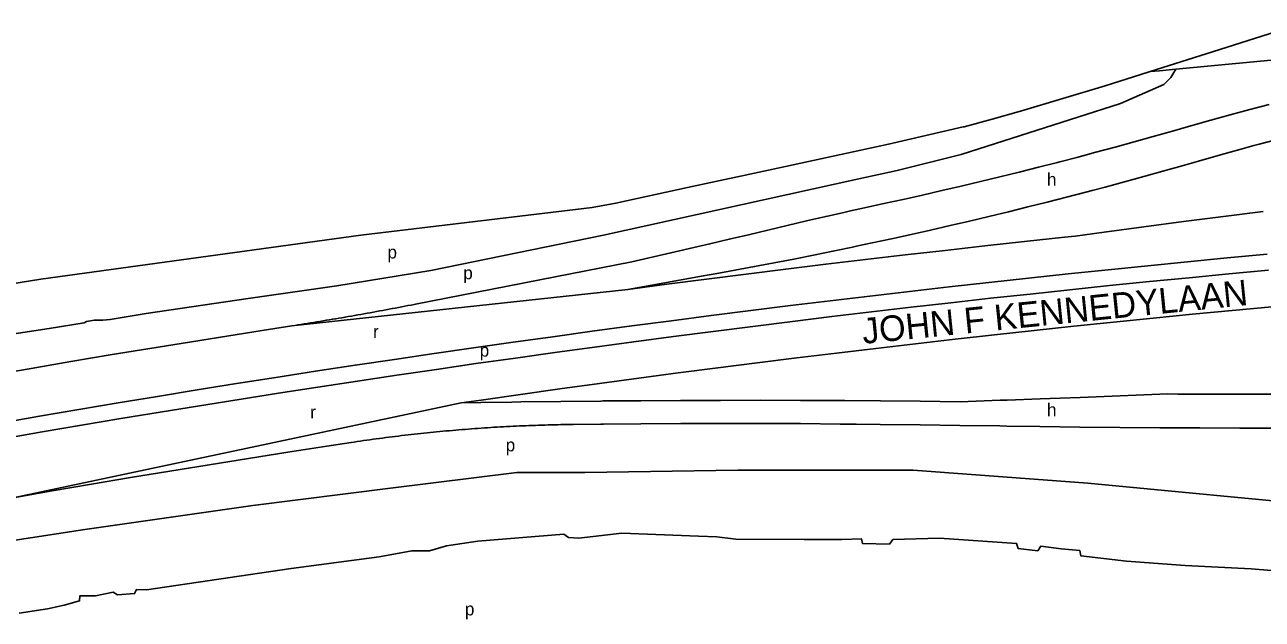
# Model space of a CAD drawing. Extents: x 159441 to 162086, y 388175 to 389787.
# Drawn here: x 159765.8 to 160153.1, y 389558.4 to 389744.4 of the extents above; entities that cross this region are included whole.
import ezdxf

# ---------------------------------------------------------------- set-up
doc = ezdxf.new("R2010")
doc.units = 0
for name, color, linetype in [('BLT_Basislijn', 7, 'Continuous'), ('BLT_Centroide', 7, 'Continuous'), ('BLT_Gemeentegrens', 7, 'Continuous'), ('BLT_Straatnaam_hoofdweg', 7, 'Continuous'), ('BLT_Vlakafsluiter', 7, 'Continuous')]:
    doc.layers.add(name, color=color, linetype=linetype)

msp = doc.modelspace()

# ---------------------------------------------------------------- linework, layer by layer
at = {"layer": 'BLT_Basislijn'}
msp.add_line((159941.02, 389604.39), (159988.95, 389605.07), dxfattribs=at)
for points in [[(160126, 389730.55), (160158.09, 389733.58), (160166.51, 389737), (160168.16, 389739.95), (160166.51, 389742.96), (160164.08, 389744.45)], [(160026.82, 389696.21), (160038.79, 389698.87), (160050.09, 389701.64), (160058.89, 389703.83), (160108.67, 389719.79), (160122.26, 389725.73), (160124.46, 389727.97), (160126, 389730.55)], [(160120.88, 389730.04), (160126, 389730.55)], [(160117.98, 389729.78), (160120.88, 389730.04)], [(160089.75, 389701.59), (160095.02, 389702.96), (160096.96, 389703.47), (160101.02, 389704.55), (160107.01, 389706.16), (160113, 389707.79), (160118.98, 389709.46), (160124.95, 389711.14), (160130.02, 389712.59), (160137.01, 389714.58), (160143.09, 389716.27), (160149.19, 389717.92), (160155.29, 389719.53)], [(160150.5, 389706.62), (160152.09, 389707.05), (160158.13, 389708.64)], [(159954.53, 389661.65), (159969.56, 389664.35), (159978.12, 389665.86), (159981.87, 389666.53), (159988.02, 389667.64), (159994.17, 389668.79), (160000.31, 389669.95), (160006.45, 389671.14), (160012.58, 389672.36), (160018.71, 389673.6), (160019.76, 389673.82), (160024.84, 389674.87), (160026.52, 389675.23), (160030.95, 389676.17), (160037.07, 389677.49), (160043.17, 389678.83), (160049.27, 389680.2), (160055.37, 389681.6), (160061.46, 389683.02), (160067.54, 389684.47), (160073.62, 389685.94), (160079.69, 389687.43), (160085.76, 389688.96), (160091.82, 389690.51), (160097.87, 389692.08), (160099.83, 389692.59), (160103.91, 389693.68), (160109.95, 389695.3), (160115.99, 389696.95), (160122.01, 389698.62), (160128.03, 389700.32), (160133.14, 389701.79), (160140.05, 389703.75), (160146.06, 389705.42), (160150.5, 389706.62)], [(159849.39, 389650.25), (159850.24, 389650.39), (159851.22, 389650.54), (159852.21, 389650.69), (159853.2, 389650.85), (159854.19, 389651.01), (159855.17, 389651.17), (159856.16, 389651.33), (159857.15, 389651.49), (159858.14, 389651.65), (159859.12, 389651.81), (159860.11, 389651.97), (159861.09, 389652.14), (159862.08, 389652.3), (159863.07, 389652.47), (159864.05, 389652.63), (159865.04, 389652.8), (159866.02, 389652.97), (159867.01, 389653.14), (159868, 389653.31), (159868.98, 389653.48), (159869.97, 389653.66), (159870.95, 389653.83), (159871.93, 389654.01), (159872.92, 389654.18), (159873.9, 389654.36), (159874.89, 389654.54), (159875.87, 389654.72), (159876.86, 389654.9), (159877.84, 389655.08), (159878.82, 389655.26), (159879.81, 389655.44), (159880.79, 389655.62), (159881.77, 389655.81), (159882.75, 389655.99), (159883.74, 389656.18), (159884.72, 389656.37), (159885.7, 389656.56), (159886.68, 389656.75), (159887.66, 389656.94), (159888.03, 389657.01), (159955.78, 389670.3), (159968, 389673.07), (159976.5, 389675.02), (159980.19, 389675.88), (159986.25, 389677.31), (159992.3, 389678.75), (159998.34, 389680.2), (160004.39, 389681.65), (160010.43, 389683.07), (160016.48, 389684.48), (160017.52, 389684.71), (160022.54, 389685.85), (160024.21, 389686.22), (160028.6, 389687.17), (160034.67, 389688.48), (160040.73, 389689.81), (160046.79, 389691.17), (160052.84, 389692.56), (160058.88, 389693.97), (160064.92, 389695.41), (160070.95, 389696.87), (160076.98, 389698.35), (160083, 389699.86), (160089.01, 389701.4), (160089.75, 389701.59)], [(159759.03, 389647.27), (159773.42, 389649.38), (159784.3, 389651.17), (159785.08, 389651.6), (159787.57, 389652.05), (159790.2, 389652.03), (159792.48, 389652.2), (159803.76, 389654.1), (159835.69, 389658.82), (159863.4, 389662.74), (159892.89, 389667.6), (159946.86, 389678.6), (160026.82, 389696.21)], [(160153.35, 389686.07), (160140.91, 389684.48), (160128.47, 389682.86), (160116.03, 389681.22), (160103.6, 389679.54), (160094.56, 389678.29), (160091.17, 389677.94), (160078.7, 389676.61), (160066.24, 389675.25), (160053.79, 389673.86), (160041.33, 389672.44), (160028.88, 389670.98), (160016.44, 389669.5), (160003.99, 389667.98), (159991.56, 389666.44), (159979.12, 389664.86), (159966.69, 389663.25), (159954.53, 389661.65)], [(160154.59, 389672.66), (160142.14, 389671.49), (160129.69, 389670.29), (160117.25, 389669.06), (160104.81, 389667.8), (160092.37, 389666.5), (160079.94, 389665.18), (160067.5, 389663.82), (160055.08, 389662.43), (160042.65, 389661.01), (160030.23, 389659.56), (160017.81, 389658.08), (160005.4, 389656.57), (159992.99, 389655.03), (159980.58, 389653.45), (159968.18, 389651.85), (159955.78, 389650.21), (159943.39, 389648.55), (159931, 389646.85), (159918.61, 389645.12), (159906.23, 389643.36), (159893.86, 389641.57), (159881.48, 389639.75), (159869.12, 389637.89), (159856.75, 389636.01), (159844.39, 389634.1), (159832.04, 389632.15), (159819.69, 389630.17), (159807.35, 389628.17), (159795.01, 389626.13), (159782.68, 389624.06), (159770.35, 389621.96), (159758.03, 389619.83)], [(159758.89, 389614.9), (159771.2, 389617.03), (159783.51, 389619.13), (159795.83, 389621.2), (159808.16, 389623.23), (159820.49, 389625.24), (159832.83, 389627.21), (159845.17, 389629.16), (159857.51, 389631.07), (159869.86, 389632.95), (159882.22, 389634.8), (159894.58, 389636.62), (159906.94, 389638.41), (159919.31, 389640.17), (159931.68, 389641.89), (159944.06, 389643.59), (159956.44, 389645.26), (159968.83, 389646.89), (159981.22, 389648.49), (159993.61, 389650.07), (160006.01, 389651.61), (160018.41, 389653.12), (160030.82, 389654.6), (160043.22, 389656.05), (160055.64, 389657.46), (160068.05, 389658.85), (160080.47, 389660.2), (160092.89, 389661.53), (160105.32, 389662.82), (160117.75, 389664.08), (160130.18, 389665.31), (160142.62, 389666.51), (160155.05, 389667.68)], [(159902.33, 389626.13), (159908.57, 389627.03), (159920.91, 389628.78), (159933.26, 389630.5), (159945.61, 389632.2), (159957.96, 389633.86), (159970.32, 389635.49), (159982.68, 389637.09), (159995.04, 389638.66), (160007.41, 389640.19), (160019.79, 389641.7), (160032.16, 389643.18), (160044.54, 389644.62), (160056.93, 389646.04), (160069.31, 389647.42), (160081.7, 389648.77), (160094.1, 389650.09), (160106.5, 389651.38), (160118.9, 389652.64), (160131.3, 389653.87), (160143.71, 389655.07), (160156.12, 389656.23)], [(159849.39, 389650.25), (159842.05, 389649.11), (159829.66, 389647.16), (159817.27, 389645.18), (159804.89, 389643.17), (159792.52, 389641.12), (159780.15, 389639.05), (159767.78, 389636.94), (159755.42, 389634.8)], [(159902.33, 389626.13), (159908.55, 389626.23), (159918.18, 389626.39), (159921.05, 389626.43), (159933.55, 389626.59), (159946.05, 389626.72), (159946.83, 389626.73), (159958.55, 389626.82), (159971.05, 389626.89), (159983.55, 389626.93), (159996.05, 389626.94), (160008.55, 389626.91), (160021.05, 389626.86), (160022.4, 389626.85), (160033.55, 389626.77), (160046.05, 389626.65), (160058.55, 389626.5), (160071.06, 389626.94), (160073.22, 389627.01), (160083.57, 389627.36), (160096.07, 389627.82), (160108.57, 389628.3), (160121.07, 389628.82), (160123.56, 389628.93), (160126.62, 389628.91), (160133.56, 389628.88), (160146.05, 389628.84), (160158.54, 389628.84)], [(160435.33, 389622.54), (160408.56, 389615.14), (160385.5, 389605.96), (160364.33, 389592.24), (160345.18, 389582), (160331.29, 389576.51), (160312.03, 389571.36), (160292.43, 389569.68), (160273.62, 389570.35), (160257.61, 389573.71), (160211.13, 389589.28), (160174.96, 389593.76), (160098.47, 389601.03), (160043.82, 389605.07), (159988.95, 389605.07)], [(159762.09, 389596.48), (159774.36, 389598.6), (159786.63, 389600.69), (159798.9, 389602.75), (159811.18, 389604.78), (159823.47, 389606.78), (159835.76, 389608.74), (159848.05, 389610.68), (159860.35, 389612.58), (159867.87, 389613.73), (159868.85, 389613.88), (159869.84, 389614.03), (159870.83, 389614.18), (159871.82, 389614.32), (159872.81, 389614.46), (159873.8, 389614.6), (159874.79, 389614.74), (159875.78, 389614.87), (159876.78, 389615.01), (159877.77, 389615.14), (159878.76, 389615.27), (159879.75, 389615.39), (159880.74, 389615.52), (159881.73, 389615.64), (159882.73, 389615.77), (159883.72, 389615.89), (159884.71, 389616), (159885.71, 389616.12), (159886.7, 389616.23), (159887.69, 389616.34), (159888.69, 389616.45), (159889.68, 389616.56), (159890.68, 389616.67), (159891.67, 389616.77), (159892.67, 389616.87), (159893.66, 389616.97), (159894.66, 389617.07), (159895.65, 389617.17), (159896.65, 389617.26), (159897.64, 389617.35), (159898.64, 389617.44), (159899.63, 389617.53), (159900.63, 389617.61), (159901.63, 389617.7), (159902.62, 389617.78), (159903.62, 389617.86), (159904.62, 389617.94), (159905.61, 389618.01), (159906.61, 389618.09), (159907.61, 389618.16), (159908.61, 389618.23), (159909.6, 389618.3), (159910.6, 389618.36), (159911.6, 389618.43), (159912.6, 389618.49), (159913.6, 389618.55), (159914.6, 389618.61), (159915.59, 389618.66), (159916.59, 389618.72), (159917.59, 389618.77), (159918.59, 389618.82), (159919.59, 389618.87), (159920.59, 389618.91), (159921.59, 389618.96), (159922.59, 389619), (159923.58, 389619.04), (159924.58, 389619.08), (159925.58, 389619.11), (159926.58, 389619.15), (159927.58, 389619.18), (159928.58, 389619.21), (159929.58, 389619.24), (159930.58, 389619.26), (159931.58, 389619.29), (159932.58, 389619.31), (159933.58, 389619.33), (159934.58, 389619.35), (159935.58, 389619.36), (159936.58, 389619.37), (159937.54, 389619.39)], [(159937.54, 389619.39), (159946.11, 389619.47), (159946.89, 389619.48), (159958.6, 389619.57), (159971.08, 389619.64), (159983.56, 389619.68), (159996.04, 389619.69), (160006.03, 389619.67), (160008.53, 389619.64), (160021.01, 389619.49), (160022.35, 389619.48), (160026, 389619.43), (160033.49, 389619.37), (160045.97, 389619.25), (160058.46, 389619.1), (160070.94, 389618.92), (160073.09, 389618.89), (160083.45, 389618.73), (160095.96, 389618.57), (160108.48, 389618.44), (160121, 389618.34), (160126.56, 389618.31), (160133.51, 389618.28), (160146.03, 389618.24), (160158.55, 389618.24)], [(159837.18, 389593.98), (159880.18, 389599.43), (159919.81, 389604.35), (159941.02, 389604.39)], [(159733.42, 389578.71), (159784.61, 389586.47), (159837.18, 389593.98)], [(160166.21, 389572.87), (160149.58, 389574.24), (160128.97, 389575.28), (160110.58, 389576.62), (160096.25, 389578.33), (160095.94, 389579.94), (160090.14, 389580.43), (160083.75, 389581.3), (160082.84, 389579.84), (160076.73, 389580.55), (160076.19, 389582.19), (160052.11, 389583.77), (160037.49, 389583.38), (160036.37, 389581.95), (160027.95, 389582.17), (160027.66, 389583.58), (160021.51, 389583.38), (160009.73, 389583.42), (159988.27, 389583.49), (159982.33, 389584.26), (159976.61, 389584.4), (159952.68, 389585.34), (159939.17, 389583.81), (159935.99, 389583.97), (159934.5, 389585.1), (159907.53, 389582.9), (159897.75, 389581.43), (159892.45, 389579.86), (159886.93, 389579.84), (159876.65, 389577.99), (159849.17, 389574.29), (159803.82, 389567.62), (159800.76, 389567.77), (159800.11, 389566.45), (159794.76, 389566.11), (159793.45, 389566.93), (159787.86, 389565.78), (159783.01, 389565.8), (159782.92, 389564.2), (159778.13, 389562.8), (159772.83, 389561.73), (159763.96, 389560.38)]]:
    msp.add_lwpolyline(points, dxfattribs=at)
at = {"layer": 'BLT_Gemeentegrens'}
for points in [[(160117.98, 389729.78), (160137.5, 389735.99), (160164.08, 389744.45)], [(160059.47, 389712.46), (160059.81, 389712.54), (160068.6, 389714.95), (160077.39, 389717.36), (160103.89, 389725.29), (160115.13, 389728.87), (160117.98, 389729.78)], [(159943.36, 389687.3), (159950.81, 389688.64), (159973.21, 389693.5), (160000, 389699.28), (160036.12, 389707.09), (160059.47, 389712.46)], [(159823.15, 389672), (159870.9, 389678.57), (159930.31, 389685.73), (159943.36, 389687.3)], [(159500, 389616.32), (159571.66, 389630.94), (159670.94, 389648.77), (159770.78, 389664.8), (159823.15, 389672)]]:
    msp.add_lwpolyline(points, dxfattribs=at)
at = {"layer": 'BLT_Vlakafsluiter'}
for p, q in [((159954.53, 389661.65), (159849.39, 389650.25)), ((159902.33, 389626.13), (159762.09, 389596.48))]:
    msp.add_line(p, q, dxfattribs=at)

# ---------------------------------------------------------------- texts
at = {"layer": 'BLT_Centroide'}
for s, p in [('h', (160085.7, 389694.05)), ('p', (159879.28, 389671.31)), ('p', (159903.01, 389664.82)), ('r', (159874.78, 389646.47)), ('p', (159908.15, 389640.61)), ('h', (160085.7, 389621.98)), ('r', (159855.09, 389621.27)), ('p', (159916.29, 389610.97)), ('p', (159903.51, 389559.65))]:
    msp.add_text(s, height=4, dxfattribs=at).set_placement(p)
at = {"layer": 'BLT_Straatnaam_hoofdweg'}
msp.add_text('JOHN F KENNEDYLAAN', height=8, rotation=5.7784, dxfattribs=at).set_placement((160028.22, 389644.58))

doc.saveas('drawing.dxf')
